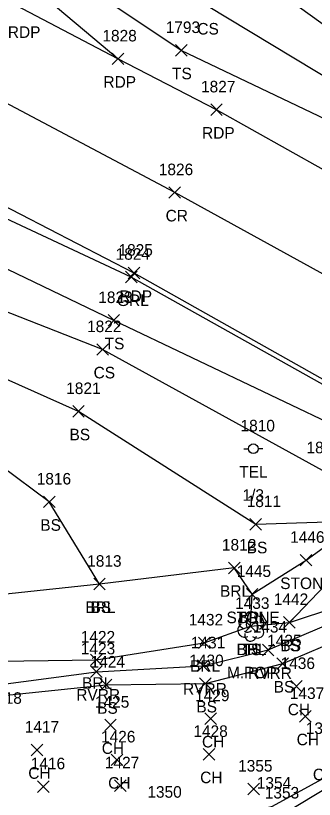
# Model space of a CAD drawing. Extents: x 1537342 to 1542195, y 163002 to 168596.
# Drawn here: x 1541684.3 to 1541736, y 163274.1 to 163409.7 of the extents above; entities that cross this region are included whole.
import ezdxf

# ---------------------------------------------------------------- set-up
doc = ezdxf.new("R2010")
doc.units = 0
for name, color, linetype in [('L_A', 7, 'Continuous'), ('L_C', 7, 'Continuous'), ('L_I', 7, 'Continuous'), ('L_TIC', 7, 'Continuous'), ('LABL', 7, 'Continuous'), ('LASF', 7, 'Continuous'), ('LAWE', 7, 'Continuous'), ('LELB', 7, 'Continuous'), ('LTD', 7, 'Continuous'), ('P_A', 7, 'Continuous'), ('P_I', 7, 'Continuous'), ('P_TIC', 7, 'Continuous'), ('PET', 7, 'Continuous'), ('PRC', 7, 'Continuous'), ('R_A', 7, 'Continuous'), ('R_I', 7, 'Continuous'), ('R_TIC', 7, 'Continuous'), ('RGR', 7, 'Continuous'), ('U_A', 7, 'Continuous'), ('U_C', 7, 'Continuous'), ('U_I', 7, 'Continuous'), ('UP', 7, 'Continuous')]:
    doc.layers.add(name, color=color, linetype=linetype)

msp = doc.modelspace()

# ---------------------------------------------------------------- linework, layer by layer
at = {"layer": 'L_TIC'}
for points in [[(1541711.96, 163402.65), (1541713.96, 163404.65)], [(1541713.96, 163402.65), (1541711.96, 163404.65)], [(1541700.3, 163355.94), (1541702.3, 163357.94)], [(1541702.3, 163355.94), (1541700.3, 163357.94)], [(1541698.36, 163350.91), (1541700.36, 163352.91)], [(1541700.36, 163350.91), (1541698.36, 163352.91)], [(1541694.19, 163340.2), (1541696.19, 163342.2)], [(1541696.19, 163340.2), (1541694.19, 163342.2)], [(1541689.14, 163324.55), (1541691.14, 163326.55)], [(1541691.14, 163324.55), (1541689.14, 163326.55)], [(1541724.85, 163320.65), (1541726.85, 163322.65)], [(1541726.85, 163320.65), (1541724.85, 163322.65)], [(1541733.55, 163314.47), (1541735.55, 163316.47)], [(1541735.55, 163314.47), (1541733.55, 163316.47)], [(1541721.13, 163313.13), (1541723.13, 163315.13)], [(1541723.13, 163313.13), (1541721.13, 163315.13)], [(1541697.82, 163310.33), (1541699.82, 163312.33)], [(1541699.82, 163310.33), (1541697.82, 163312.33)], [(1541697.82, 163310.33), (1541699.82, 163312.33)], [(1541699.82, 163310.33), (1541697.82, 163312.33)], [(1541724.24, 163308.57), (1541726.24, 163310.57)], [(1541726.24, 163308.57), (1541724.24, 163310.57)], [(1541724.24, 163308.57), (1541726.24, 163310.57)], [(1541726.24, 163308.57), (1541724.24, 163310.57)], [(1541730.67, 163303.71), (1541732.67, 163305.71)], [(1541732.67, 163303.71), (1541730.67, 163305.71)], [(1541730.67, 163303.71), (1541732.67, 163305.71)], [(1541732.67, 163303.71), (1541730.67, 163305.71)], [(1541723.97, 163303.04), (1541725.97, 163305.04)], [(1541725.97, 163303.04), (1541723.97, 163305.04)], [(1541723.97, 163303.04), (1541725.97, 163305.04)], [(1541725.97, 163303.04), (1541723.97, 163305.04)], [(1541715.95, 163300.17), (1541717.95, 163302.17)], [(1541717.95, 163300.17), (1541715.95, 163302.17)], [(1541727.01, 163298.94), (1541729.01, 163300.94)], [(1541729.01, 163298.94), (1541727.01, 163300.94)], [(1541697.27, 163297.22), (1541699.27, 163299.22)], [(1541699.27, 163297.22), (1541697.27, 163299.22)], [(1541729.52, 163296.57), (1541731.52, 163298.57)], [(1541731.52, 163296.57), (1541729.52, 163298.57)], [(1541697.28, 163295.18), (1541699.28, 163297.18)], [(1541699.28, 163295.18), (1541697.28, 163297.18)], [(1541715.76, 163296.21), (1541717.76, 163298.21)], [(1541717.76, 163296.21), (1541715.76, 163298.21)], [(1541698.97, 163292.9), (1541700.97, 163294.9)], [(1541700.97, 163292.9), (1541698.97, 163294.9)], [(1541716.14, 163293.13), (1541718.14, 163295.13)], [(1541718.14, 163293.13), (1541716.14, 163295.13)], [(1541731.9, 163292.64), (1541733.9, 163294.64)], [(1541733.9, 163292.64), (1541731.9, 163294.64)], [(1541717.06, 163287.07), (1541719.06, 163289.07)], [(1541719.06, 163287.07), (1541717.06, 163289.07)], [(1541733.45, 163287.45), (1541735.45, 163289.45)], [(1541735.45, 163287.45), (1541733.45, 163289.45)], [(1541699.72, 163285.95), (1541701.72, 163287.95)], [(1541701.72, 163285.95), (1541699.72, 163287.95)], [(1541687.01, 163281.65), (1541689.01, 163283.65)], [(1541689.01, 163281.65), (1541687.01, 163283.65)], [(1541716.75, 163280.89), (1541718.75, 163282.89)], [(1541718.75, 163280.89), (1541716.75, 163282.89)], [(1541700.83, 163279.94), (1541702.83, 163281.94)], [(1541702.83, 163279.94), (1541700.83, 163281.94)], [(1541688.11, 163275.3), (1541690.11, 163277.3)], [(1541690.11, 163275.3), (1541688.11, 163277.3)], [(1541701.44, 163275.46), (1541703.44, 163277.46)], [(1541703.44, 163275.46), (1541701.44, 163277.46)], [(1541724.49, 163274.9), (1541726.49, 163276.9)], [(1541726.49, 163274.9), (1541724.49, 163276.9)]]:
    msp.add_lwpolyline(points, dxfattribs=at)
at = {"layer": 'LABL'}
for points in [[(1541844.34, 163370.6), (1541821.33, 163359.44), (1541813.12, 163355.49), (1541797.38, 163365.13), (1541723.78, 163418.04)], [(1541677.36, 163297.92), (1541698.27, 163298.22), (1541716.95, 163301.17), (1541724.97, 163304.04), (1541725.24, 163309.57), (1541722.13, 163314.13), (1541698.82, 163311.33), (1541669.13, 163308.16)]]:
    msp.add_lwpolyline(points, dxfattribs=at)
at = {"layer": 'LASF'}
msp.add_lwpolyline([(1541725.24, 163309.57), (1541734.55, 163315.47), (1541742.75, 163321.41), (1541743.53, 163322.21), (1541748.76, 163326.38), (1541753.47, 163327.4)], dxfattribs=at)
at = {"layer": 'LAWE'}
for points in [[(1541677.78, 163293.44), (1541698.28, 163296.18), (1541716.76, 163297.21), (1541728.01, 163299.94), (1541740.07, 163305.1), (1541745.43, 163310.81), (1541754.16, 163316.75), (1541763.56, 163326.93)], [(1541697.57, 163262.54), (1541711.73, 163266.96), (1541730.1, 163271.24), (1541739.51, 163276.96), (1541746.47, 163282.88), (1541755.03, 163290.89), (1541767.29, 163298.26), (1541776.81, 163302.23), (1541780.9, 163305.15), (1541791.03, 163307.2)]]:
    msp.add_lwpolyline(points, dxfattribs=at)
at = {"layer": 'LELB'}
for points in [[(1541813.12, 163355.49), (1541807.59, 163352.29), (1541792.75, 163363.67), (1541773.45, 163377.86), (1541766.85, 163384.06), (1541755.11, 163388.66), (1541717.31, 163411.39), (1541693.13, 163425.74), (1541646.55, 163461.21), (1541615.06, 163486.33), (1541589.07, 163507.09)], [(1541806.46, 163346.35), (1541770.85, 163375.53), (1541766.11, 163382.32), (1541753.11, 163384.46), (1541712.96, 163403.65), (1541689.28, 163419.49), (1541645.56, 163455.19), (1541611.14, 163481.6), (1541585.04, 163504.65)], [(1541762.76, 163328.26), (1541741.98, 163337.57), (1541701.3, 163356.94), (1541664.55, 163374.56), (1541614.42, 163401.42), (1541584.18, 163419.26), (1541552.3, 163432.58), (1541546.69, 163431.72)], [(1541753.68, 163328.14), (1541737.41, 163330.95), (1541699.36, 163351.91), (1541657.86, 163368.16), (1541610.38, 163396.93), (1541582.75, 163415.8), (1541550.64, 163428.77), (1541544.42, 163427.2), (1541540.39, 163420.64), (1541544.66, 163416.07), (1541557.53, 163413.19)], [(1541698.82, 163311.33), (1541690.14, 163325.55), (1541673.34, 163337.99), (1541655.18, 163337.59), (1541641.59, 163348.42), (1541603.88, 163376.84), (1541575.03, 163398.69), (1541557.53, 163413.19), (1541544.03, 163423.1), (1541544.73, 163424.91), (1541556.53, 163422.33)], [(1541743.53, 163322.21), (1541725.85, 163321.65), (1541695.19, 163341.2), (1541650.61, 163361.07), (1541607.09, 163386.64), (1541578.45, 163407.49), (1541556.53, 163422.33)], [(1541680.48, 163291.86), (1541699.97, 163293.9), (1541717.14, 163294.13), (1541730.52, 163297.57), (1541741.65, 163302.35), (1541748.18, 163305.38), (1541748.08, 163309.08), (1541755.23, 163315.37), (1541766.51, 163324.36), (1541774.32, 163324.47), (1541783.87, 163329.52), (1541794.38, 163332.12), (1541806.54, 163337.4), (1541818.82, 163343.08), (1541839.23, 163350.56), (1541851.31, 163354.65), (1541860.2, 163362.66), (1541879.49, 163366.97), (1541895.13, 163366.2), (1541914.25, 163372.83), (1541910.85, 163375.47), (1541893.7, 163387.22), (1541872.66, 163402.01), (1541849.05, 163411.83)], [(1541724.97, 163304.04), (1541731.67, 163304.71), (1541739.88, 163307.37), (1541744.73, 163312.18), (1541751.22, 163318.19), (1541759.41, 163327.06)], [(1541731.67, 163304.71), (1541739.13, 163312.48), (1541744.49, 163320.37), (1541749.33, 163319.75), (1541754.81, 163327.19)], [(1541697.38, 163265.2), (1541711.19, 163268.47), (1541728.73, 163272.94), (1541738.54, 163278.3), (1541744.94, 163284.53), (1541750.45, 163291.78), (1541762.36, 163297.06), (1541764.63, 163298.71), (1541768.94, 163301.66), (1541775.91, 163303.98), (1541780.38, 163306.77), (1541791.08, 163308.95)]]:
    msp.add_lwpolyline(points, dxfattribs=at)
at = {"layer": 'LTD'}
msp.add_line((1541724.97, 163304.04), (1541724.97, 163304.04), dxfattribs=at)
msp.add_line((1541724.97, 163304.04), (1541724.97, 163304.04), dxfattribs=at)
msp.add_arc((1541725.02, 163305.48), 1.05, 335.5272, 180.9563, dxfattribs=at)
for centre, major_axis, ratio, start_param, end_param in [((1541724.18, 163304.71), (1.21, -0.51), 0.895232, 1.570796, 4.712389), ((1541724.77, 163304.5), (-0.208, -0.792), 0.645439, 3.141593, 6.283185), ((1541726.02, 163304.63), (-1.14, -0.48), 0.949671, 1.570796, 4.712389), ((1541723.89, 163303.33), (0.58, -1.04), 0.959034, 3.141593, 6.283185), ((1541725.47, 163303.88), (-0.5, 0.667), 0.989748, 3.141593, 6.283185), ((1541725.97, 163303.21), (-1.09, 0.79), 0.841452, 1.570796, 4.712389), ((1541724.97, 163302.54), (0.26, 1.06), 0.942809, 1.570796, 4.712389), ((1541724.52, 163303.29), (-0.625, -0.083), 0.423636, 0, 3.141593)]:
    msp.add_ellipse(centre, major_axis=major_axis, ratio=ratio, start_param=start_param, end_param=end_param, dxfattribs=at)
at = {"layer": 'P_TIC'}
for points in [[(1541701.01, 163401.19), (1541703.01, 163403.19)], [(1541703.01, 163401.19), (1541701.01, 163403.19)], [(1541701.01, 163401.19), (1541703.01, 163403.19)], [(1541703.01, 163401.19), (1541701.01, 163403.19)], [(1541718.07, 163392.38), (1541720.07, 163394.38)], [(1541720.07, 163392.38), (1541718.07, 163394.38)], [(1541710.83, 163378.06), (1541712.83, 163380.06)], [(1541712.83, 163378.06), (1541710.83, 163380.06)], [(1541703.8, 163364.13), (1541705.8, 163366.13)], [(1541705.8, 163364.13), (1541703.8, 163366.13)]]:
    msp.add_lwpolyline(points, dxfattribs=at)
at = {"layer": 'PET'}
for points in [[(1541702.01, 163402.19), (1541687.22, 163414.66), (1541642.2, 163448.26), (1541608.31, 163479.46), (1541580.56, 163501.03)], [(1541804.88, 163343.94), (1541781.94, 163357.9), (1541762.27, 163369.13), (1541719.07, 163393.38), (1541702.01, 163402.19), (1541685.47, 163410.81), (1541633.42, 163436.22), (1541598.66, 163451.94), (1541573.75, 163461.19), (1541557.97, 163467.97)], [(1541804.88, 163343.94), (1541786.3, 163336.28), (1541767.14, 163328.63), (1541744.37, 163342.88), (1541704.8, 163365.13), (1541670.45, 163382.89), (1541617.1, 163408.36), (1541585.57, 163422.3), (1541550.23, 163436.7), (1541542.2, 163439.81)]]:
    msp.add_lwpolyline(points, dxfattribs=at)
at = {"layer": 'PRC'}
msp.add_lwpolyline([(1541786.3, 163336.28), (1541753.03, 163356.38), (1541711.83, 163379.06), (1541677.63, 163397.19), (1541623.38, 163422.53), (1541592.11, 163436.74), (1541548.19, 163454.58)], dxfattribs=at)
at = {"layer": 'R_TIC'}
for points in [[(1541703.31, 163363.43), (1541705.31, 163365.43)], [(1541705.31, 163363.43), (1541703.31, 163365.43)]]:
    msp.add_lwpolyline(points, dxfattribs=at)
at = {"layer": 'RGR'}
msp.add_lwpolyline([(1541766.69, 163328.4), (1541744.13, 163342.08), (1541704.31, 163364.43), (1541668.89, 163380.95)], dxfattribs=at)
at = {"layer": 'UP'}
for p, q in [((1541723.77, 163334.73), (1541724.6, 163334.73)), ((1541725.43, 163334.74), (1541725.43, 163334.74)), ((1541727.1, 163334.74), (1541726.26, 163334.74)), ((1541726.26, 163334.74), (1541726.26, 163334.74)), ((1541727.1, 163334.74), (1541727.1, 163334.74))]:
    msp.add_line(p, q, dxfattribs=at)
msp.add_circle((1541725.43, 163334.74), 0.833, dxfattribs=at)

# ---------------------------------------------------------------- texts
at = {"layer": 'L_A'}
for s, p in [('CS', (1541715.75, 163406.39)), ('TS', (1541711.37, 163398.65)), ('TS', (1541699.71, 163351.94)), ('CS', (1541697.8, 163346.91)), ('BS', (1541693.63, 163336.2)), ('BS', (1541688.58, 163320.55)), ('BS', (1541724.29, 163316.65)), ('STONE', (1541730.09, 163310.47)), ('BRL', (1541719.67, 163309.13)), ('BRL', (1541696.36, 163306.33)), ('BS', (1541697.26, 163306.33)), ('STONE', (1541720.79, 163304.57)), ('BRL', (1541722.79, 163304.57)), ('TS', (1541730.08, 163299.71)), ('BS', (1541730.11, 163299.71)), ('BRL', (1541722.52, 163299.04)), ('TS', (1541723.38, 163299.04)), ('H', (1541724.41, 163299.04)), ('BRL', (1541714.49, 163296.17)), ('RVRR', (1541724.53, 163294.94)), ('BRL', (1541695.81, 163293.22)), ('BS', (1541728.96, 163292.57)), ('RVRR', (1541694.8, 163291.18)), ('RVRR', (1541713.27, 163292.21)), ('BS', (1541698.41, 163288.9)), ('BS', (1541715.58, 163289.13)), ('CH', (1541731.39, 163288.64)), ('CH', (1541716.55, 163283.07)), ('CH', (1541732.93, 163283.45)), ('CH', (1541699.21, 163281.95)), ('CH', (1541686.5, 163277.65)), ('CH', (1541716.24, 163276.89)), ('CH', (1541735.74, 163277.4)), ('CH', (1541700.32, 163275.94))]:
    msp.add_text(s, height=2, dxfattribs=at).set_placement(p)
at = {"layer": 'L_C'}
msp.add_text('M.POP', height=2, dxfattribs=at).set_placement((1541720.87, 163295.04))
at = {"layer": 'L_I'}
for s, p in [('1793', (1541710.27, 163406.65)), ('1823', (1541698.61, 163359.94)), ('1822', (1541696.67, 163354.91)), ('1821', (1541693.06, 163344.2)), ('1809', (1541734.63, 163333.95)), ('1816', (1541687.96, 163328.55)), ('1811', (1541724.29, 163324.65)), ('1446', (1541731.8, 163318.47)), ('1812', (1541720, 163317.13)), ('1813', (1541696.69, 163314.33)), ('1813', (1541696.69, 163314.33)), ('1445', (1541722.55, 163312.57)), ('1445', (1541722.55, 163312.57)), ('1442', (1541728.98, 163307.71)), ('1442', (1541728.98, 163307.71)), ('1433', (1541722.28, 163307.04)), ('1433', (1541722.28, 163307.04)), ('1433', (1541722.28, 163307.04)), ('1432', (1541714.26, 163304.17)), ('1434', (1541725.32, 163302.94)), ('1422', (1541695.58, 163301.22)), ('1435', (1541727.83, 163300.57)), ('1423', (1541695.59, 163299.18)), ('1431', (1541714.63, 163300.21)), ('1424', (1541697.28, 163296.9)), ('1430', (1541714.36, 163297.13)), ('1436', (1541730.15, 163296.64)), ('1429', (1541715.36, 163291.07)), ('1437', (1541731.75, 163291.45)), ('1418', (1541679.44, 163290.62)), ('1425', (1541698.03, 163289.95)), ('1417', (1541685.89, 163285.65)), ('1428', (1541715.06, 163284.89)), ('1356', (1541734.51, 163285.4)), ('1426', (1541699.08, 163283.94)), ('1416', (1541686.93, 163279.3)), ('1427', (1541699.75, 163279.46)), ('1355', (1541722.8, 163278.9)), ('1354', (1541726.03, 163275.94)), ('1350', (1541707.1, 163274.38)), ('1353', (1541727.41, 163274.24))]:
    msp.add_text(s, height=2, dxfattribs=at).set_placement(p)
at = {"layer": 'P_A'}
for s, p in [('RDP', (1541682.96, 163405.81)), ('RDP', (1541699.5, 163397.19)), ('RDP', (1541699.5, 163397.19)), ('RDP', (1541716.56, 163388.38)), ('CR', (1541710.26, 163374.06)), ('RDP', (1541702.28, 163360.13))]:
    msp.add_text(s, height=2, dxfattribs=at).set_placement(p)
at = {"layer": 'P_I'}
for s, p in [('1828', (1541699.32, 163405.19)), ('1828', (1541699.32, 163405.19)), ('1827', (1541716.38, 163396.38)), ('1826', (1541709.08, 163382.06)), ('1825', (1541702.1, 163368.13))]:
    msp.add_text(s, height=2, dxfattribs=at).set_placement(p)
at = {"layer": 'R_A'}
msp.add_text('GRL', height=2, dxfattribs=at).set_placement((1541701.85, 163359.43))
at = {"layer": 'R_I'}
msp.add_text('1824', height=2, dxfattribs=at).set_placement((1541701.61, 163367.43))
at = {"layer": 'U_A'}
msp.add_text('TEL', height=2, dxfattribs=at).set_placement((1541722.99, 163329.74))
at = {"layer": 'U_C'}
msp.add_text('1/3', height=2, dxfattribs=at).set_placement((1541723.56, 163325.74))
at = {"layer": 'U_I'}
msp.add_text('1810', height=2, dxfattribs=at).set_placement((1541723.22, 163337.74))

doc.saveas('drawing.dxf')
